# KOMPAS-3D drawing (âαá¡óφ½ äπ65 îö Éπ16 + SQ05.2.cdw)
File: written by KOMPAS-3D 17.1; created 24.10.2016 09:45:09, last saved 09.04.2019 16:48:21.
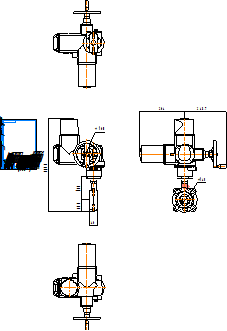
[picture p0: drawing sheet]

Sheet 1: A4, portrait

Title block, sheet 1: name: Гранвэл Ду65 МФ Ру16 + / SQ05.2; material: Внимание! Данный продукт является объектом авторского права ООО «Торговый Дом АДЛ». / Запрещается изменение, копирование, распространение / (в том числе путем копирования на другие сайты и ресурсы в Интернете) / или любое иное использование информации и объектов без предварительного / согласия правообладателя (ООО «Торговый Дом АДЛ»).; mass: 25,6; sheets: 1; organisation: ООО "Торговый дом АДЛ"; sheet format: A4; stored path: \\adlc.lan\data\АДЛ_ПКД\3D-модели\ADL production\Дисковые поворотные затворы ГРАНВЭЛ\межфланцевый с эл.приводом Auma Ру 16\KOMPAS 2D\Гранвэл Ду65 МФ Ру16 + SQ05.2.cdw

Views: Вид 1, Проекционный вид 2, Проекционный вид 3, Проекционный вид 4
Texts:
  Klimkovich
  ADL
Dimensions and other numbers on the sheet: 46; 160; 135; 68,8; 547,3; 145; 264; 248,7; 1:1; 1; 25,6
